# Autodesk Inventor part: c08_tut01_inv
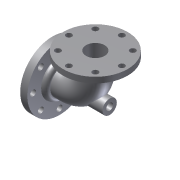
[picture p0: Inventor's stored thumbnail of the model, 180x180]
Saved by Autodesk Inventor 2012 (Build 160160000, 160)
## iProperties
Created: 2010-03
Part Number: c08_tut01_inv
Document SubType Name: Modeling
Designer: CADSoft
Density: 1 g/cm^3
Material: Default
Author: CADSoft
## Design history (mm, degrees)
sketch "Sketch1"
  geometry: 1 further point
sketch "Sketch2"
  geometry: L1 (-90, 35)-(-90, 0); L2 (0, -90)-(35, -90); A1 r 90 centre (0, 0) between (-90, 0) and (0, -90); 1 further point
  constraints: 4 end point, 2 point on circle, 2 tangent, 1 centre point, 1 coincident, 1 perpendicular, 1 vertical
  dimensions: "d0" = 35 distance of L1.start L1.end; "d1" = 35 distance of L2.start L2.end; "d2" = 90 radius of A1
workplane "Work Plane1"
sketch "Sketch3"
  geometry: C1 r 48.5 at (0, 0); 1 further point
  constraints: 1 centre point
  dimensions: "d3" = 97 diameter of C1
sweep "Sweep1" sketch "Sketch3" dims "d4" = 0
shell "Shell1" dims "d5" = 16
sketch "Sketch5"
  geometry: C1 r 32.5 at (0, 0) reference; C2 r 48.5 at (0, 0) reference; C3 r 32.5 at (0, 0); C4 r 112.5 at (0, 0); 1 further point
  constraints: 2 centre point, 2 coincident, 1 concentric
  dimensions: "d6" = 225 diameter of C4
extrude "Extrusion1" join sketch "Sketch5" distance "d7" = 20; taper "d8" = 0 deg
sketch "Sketch6"
  geometry: C1 r 32.5 at (0, 0) reference; C2 r 48.5 at (0, 0) reference; C3 r 32.5 at (0, 0); C4 r 112.5 at (0, 0); 1 further point
  constraints: 2 centre point, 2 coincident, 1 concentric
  dimensions: "d9" = 225 diameter of C4
extrude "Extrusion5" join sketch "Sketch6" distance "d21" = 25; taper "d22" = 0 deg
sketch "Sketch10"
  geometry: C1 r 48.5 at (0, 0) reference; C2 r 112.5 at (0, 0) reference; C3 r 64.5 at (0, 0); 1 further point
  constraints: 1 centre point, 1 coincident
  dimensions: "d23" = 129 diameter of C3
extrude "Extrusion6" join sketch "Sketch10" distance "d24" = 16; taper "d25" = 0 deg
fillet "Fillet3" dims "d26" = 16
workplane "Work Plane2"
sketch "Sketch11"
  geometry: L1 (-145, -112.5)-(-145, 112.5) reference; C1 r 25 at (0, 0); 1 further point
  constraints: 1 centre point
  dimensions: "d28" = 50 diameter of C1; "d29" = 145 distance from line of C1.centre L1
extrude "Extrusion7" join sketch "Sketch11" stored distance "d30" = 16; taper "d31" = 0 deg
hole "Hole1" diameter "d34" = 20; stored, may be unused: countersink angle "d38" = 90 deg, drill point angle "d40" = 0 deg; dims "d32" = 10, "d33" = 10, "d35" = 6, "d36" = 24, "d37" = 28, "d39" = 8
sketch "Sketch12"
  geometry: C1 r 32.5 at (0, 0) reference; 2 further points
  constraints: 1 horizontal alignment
  dimensions: "d41" = 92.5 distance of point (92.5, 0) C1.centre
hole "Hole2" sketch "Sketch12" at (92.5, 0) diameter "d42" = 20; stored, may be unused: countersink angle "d46" = 90 deg, drill point angle "d48" = 118 deg; dims "d43" = 6, "d44" = 24, "d45" = 28, "d47" = 2
pattern_circular "Circular Pattern1" dims angle "d50" = 360 deg
sketch "Sketch13"
  geometry: C1 r 48.5 at (0, 0) reference; 2 further points
  constraints: 1 horizontal alignment
  dimensions: "d52" = 92.5 distance of C1.centre point (-92.5, 0)
hole "Hole3" sketch "Sketch13" at (-92.5, 0) diameter "d53" = 20.5; stored, may be unused: countersink angle "d57" = 90 deg, drill point angle "d59" = 118 deg; dims "d54" = 6, "d55" = 24, "d56" = 28, "d58" = 2
pattern_circular "Circular Pattern2" dims angle "d61" = 360 deg
body "Solid1"
other parameters: "d27" = 175
